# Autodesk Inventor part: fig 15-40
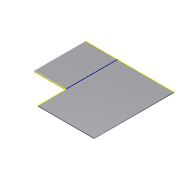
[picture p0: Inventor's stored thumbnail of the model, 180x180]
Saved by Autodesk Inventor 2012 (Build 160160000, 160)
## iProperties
Created: 2005-03
Part Number: fig 15-40
Document SubType Name: Sheet Metal
Designer: CADCIM
Manufacturer: Standard
Standards Organization: Custom
Density: 1 g/cm^3
Sheet Metal Rule: Default
Material: Default
Author: CADCIM
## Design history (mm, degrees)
node "Face1"
  sketch "Sketch1"
    geometry: L1 (31.393, 35.714)-(-19.875, 35.714); L2 (-19.875, 35.714)-(-19.875, 5.625); L3 (-19.875, 5.625)-(-1.5, 5.625); L4 (-1.5, 5.625)-(-1.5, -10.705); L5 (-1.5, -10.705)-(31.393, -10.705); L6 (31.393, -10.705)-(31.393, 35.714)
    constraints: 12 end point, 4 parallel, 1 horizontal, 1 perpendicular
sketch "Sketch3"
  geometry: L1 (18.375, -30.089)-(18.375, 0); L2 (18.375, -46.42)-(18.375, -30.089) reference; L3 (18.375, -30.089)-(0, -30.089) reference; L4 (0, 0)-(51.268, 0) reference
  constraints: 3 point on line, 2 end point, 1 vertical
body "Solid1"
face "Plate1" dims "Thickness" = 0.5
other parameters: "BendRadius" = 0.5 (= Thickness), "BendReliefWidth" = 0.5 (= Thickness), "BendReliefDepth" = 0.25 (= 0.5 x Thickness), "CornerReliefSize" = 2 (= 4 x Thickness), "SeamGap" = 0.01, "MinimumRemnant" = 1 (= 2 x Thickness), "TransitionRadius" = 0.5 (= BendRadius), "d0" = 0.5 (= BendRadius), "JacobiRadiusSize" = 0.5 (= Thickness), "GapSize" = 0.5 (= Thickness)
